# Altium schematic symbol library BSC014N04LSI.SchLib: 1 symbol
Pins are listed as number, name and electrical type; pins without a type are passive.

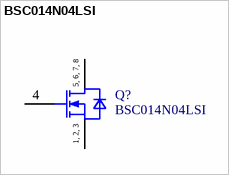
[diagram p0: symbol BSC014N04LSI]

## BSC014N04LSI
designator Q?
Insulated-Gate Field-Effect Transistor (IGFET), N-Channel, Enhancement, Body Diode, Pin 1 Source, 2 Source, 3 Source, 4 Gate, 5 Drain, 6 Drain, 7 Drain, 8 Drain, 8 Pins; Manufacturer: Infineon Technologies
pins: 1 SOURCE, 2 SOURCE, 3 SOURCE, 4 GATE, 5 DRAIN, 6 DRAIN, 7 DRAIN, 8 DRAIN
